(* Logix 5000 project; controller DNP3Master vendor 1 type 14 code 96 rev 19.13; software revision 19.01; part 4 of 5 *)

ADD_ON_INSTRUCTION PSDNP3EventG30V02   (* revision 1.0, vendor ProSoft Technology Inc *)
// Processes DNP3 Event and updates corresponding static DNP3 object. (Report by Exception.)
// G30V01 - Analog Input - 16bit with Status
VAR_IN_OUT
   EventBuffer : PSDNP3MasterEvent[1]; {required}
END_VAR
VAR_INPUT
   BufferSize : DINT; {required}
   CurrentBufferIndex : DINT; {required}
   Reset : BOOL; {required}
   OutstationNodeAddress : INT; {required}
   OutstationIPAddress0 : INT; {required}
   OutstationIPAddress1 : INT; {required}
   OutstationIPAddress2 : INT; {required}
   OutstationIPAddress3 : INT; {required}
END_VAR
VAR_IN_OUT
   DNP3StaticObject : PSDNP3AnalogInput16Flag[1]; {required}
END_VAR
VAR_INPUT
   MaxtElementCount : DINT; {required}
END_VAR
VAR_OUTPUT
   EventsProcessed : DINT; {access Read Only, visible}
   LastElementIndex : DINT; {access Read Only, visible}
   LastValue : DINT; {access Read Only, visible}
   LastStatus : SINT; {access Read Only, visible}
   CurrentUnloadIndex : DINT; {access Read Only, visible}
END_VAR
VAR
   UnloadIndex : DINT; {access None}
   EnableInTemp : BOOL; {access None}
   InitialScan : BOOL; {access None}
   EntryValidForProcessing : BOOL; {access None}
   ElementIndex : DINT; {access None}
   NextIndex : DINT; {access None}
   ResetPulse : BOOL; {access None}
   ResetONS : BOOL; {access None}
END_VAR

ROUTINE Logic   (* ladder *)
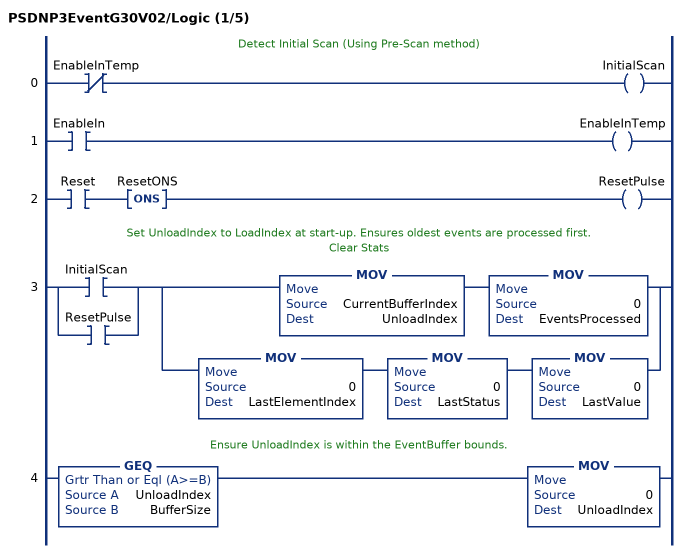
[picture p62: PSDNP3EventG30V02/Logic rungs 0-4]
   // Detect Initial Scan (Using Pre-Scan method)
   0: XIO(EnableInTemp)OTE(InitialScan);
   1: XIC(EnableIn)OTE(EnableInTemp);
   2: XIC(Reset)ONS(ResetONS)OTE(ResetPulse);
   // Set UnloadIndex to LoadIndex at start-up. Ensures oldest events are processed first.
   // Clear Stats
   3: [XIC(InitialScan) ,XIC(ResetPulse) ][MOV(CurrentBufferIndex,UnloadIndex) MOV(0,EventsProcessed) ,MOV(0,LastElementIndex) MOV(0,LastStatus) MOV(0,LastValue) ];
   // Ensure UnloadIndex is within the EventBuffer bounds.
   4: GEQ(UnloadIndex,BufferSize)MOV(0,UnloadIndex);
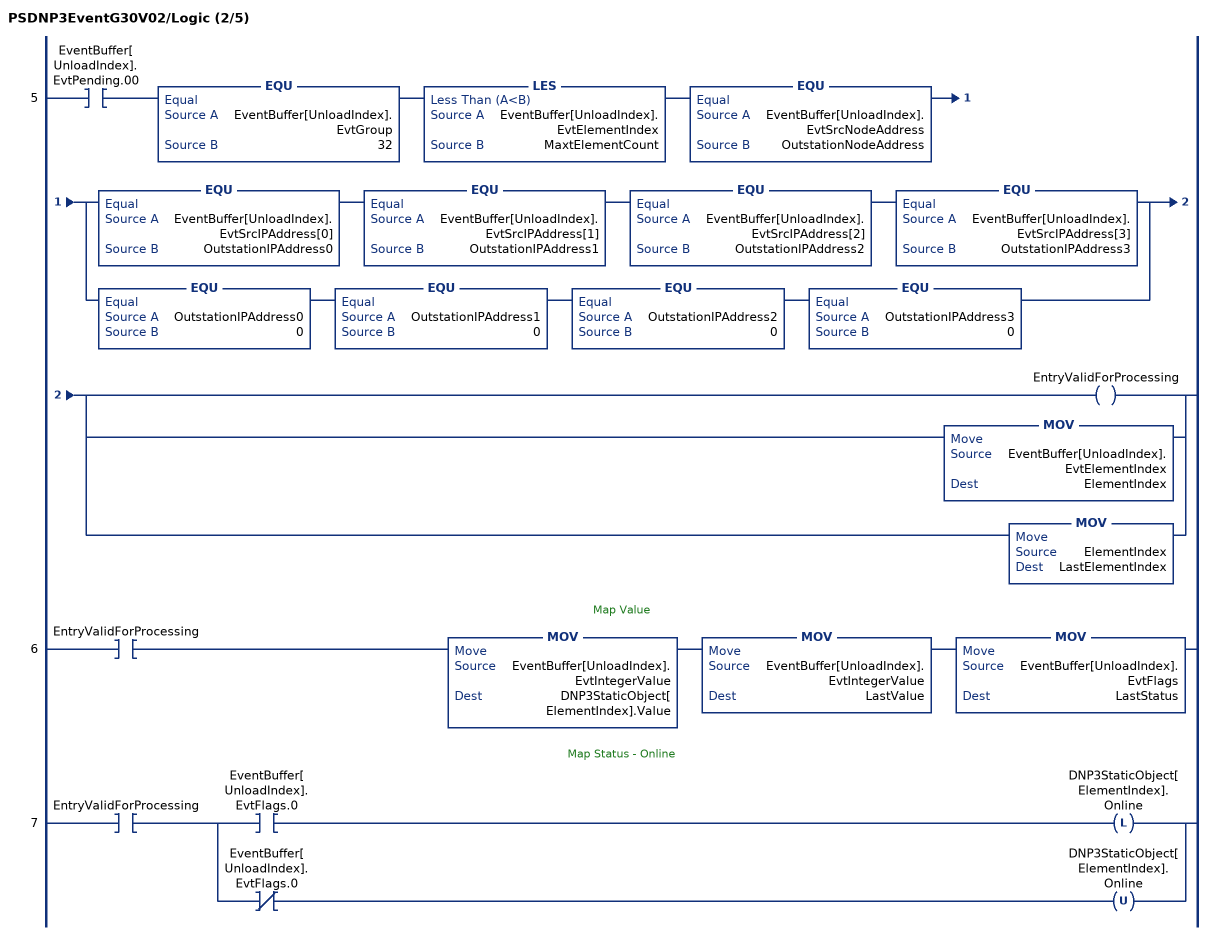
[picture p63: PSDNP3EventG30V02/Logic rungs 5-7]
   5: XIC(EventBuffer[UnloadIndex].EvtPending.00)EQU(EventBuffer[UnloadIndex].EvtGroup,32)LES(EventBuffer[UnloadIndex].EvtElementIndex,MaxtElementCount)EQU(EventBuffer[UnloadIndex].EvtSrcNodeAddress,OutstationNodeAddress)[EQU(EventBuffer[UnloadIndex].EvtSrcIPAddress[0],OutstationIPAddress0) EQU(EventBuffer[UnloadIndex].EvtSrcIPAddress[1],OutstationIPAddress1) EQU(EventBuffer[UnloadIndex].EvtSrcIPAddress[2],OutstationIPAddress2) EQU(EventBuffer[UnloadIndex].EvtSrcIPAddress[3],OutstationIPAddress3) ,EQU(OutstationIPAddress0,0) EQU(OutstationIPAddress1,0) EQU(OutstationIPAddress2,0) EQU(OutstationIPAddress3,0) ][OTE(EntryValidForProcessing) ,MOV(EventBuffer[UnloadIndex].EvtElementIndex,ElementIndex) ,MOV(ElementIndex,LastElementIndex) ];
   // Map Value
   6: XIC(EntryValidForProcessing)MOV(EventBuffer[UnloadIndex].EvtIntegerValue,DNP3StaticObject[ElementIndex].Value)MOV(EventBuffer[UnloadIndex].EvtIntegerValue,LastValue)MOV(EventBuffer[UnloadIndex].EvtFlags,LastStatus);
   // Map Status - Online
   7: XIC(EntryValidForProcessing)[XIC(EventBuffer[UnloadIndex].EvtFlags.0) OTL(DNP3StaticObject[ElementIndex].Online) ,XIO(EventBuffer[UnloadIndex].EvtFlags.0) OTU(DNP3StaticObject[ElementIndex].Online) ];
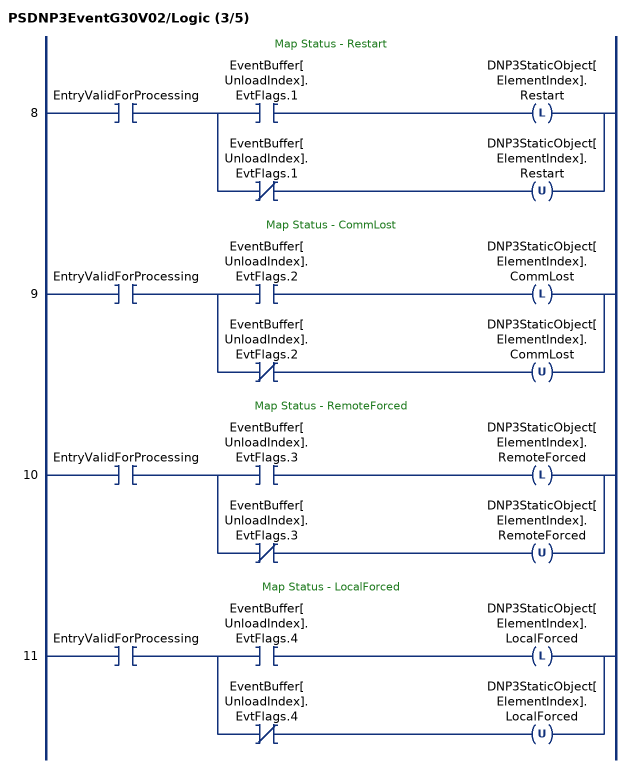
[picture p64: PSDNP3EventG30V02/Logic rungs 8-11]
   // Map Status - Restart
   8: XIC(EntryValidForProcessing)[XIC(EventBuffer[UnloadIndex].EvtFlags.1) OTL(DNP3StaticObject[ElementIndex].Restart) ,XIO(EventBuffer[UnloadIndex].EvtFlags.1) OTU(DNP3StaticObject[ElementIndex].Restart) ];
   // Map Status - CommLost
   9: XIC(EntryValidForProcessing)[XIC(EventBuffer[UnloadIndex].EvtFlags.2) OTL(DNP3StaticObject[ElementIndex].CommLost) ,XIO(EventBuffer[UnloadIndex].EvtFlags.2) OTU(DNP3StaticObject[ElementIndex].CommLost) ];
   // Map Status - RemoteForced
   10: XIC(EntryValidForProcessing)[XIC(EventBuffer[UnloadIndex].EvtFlags.3) OTL(DNP3StaticObject[ElementIndex].RemoteForced) ,XIO(EventBuffer[UnloadIndex].EvtFlags.3) OTU(DNP3StaticObject[ElementIndex].RemoteForced) ];
   // Map Status - LocalForced
   11: XIC(EntryValidForProcessing)[XIC(EventBuffer[UnloadIndex].EvtFlags.4) OTL(DNP3StaticObject[ElementIndex].LocalForced) ,XIO(EventBuffer[UnloadIndex].EvtFlags.4) OTU(DNP3StaticObject[ElementIndex].LocalForced) ];
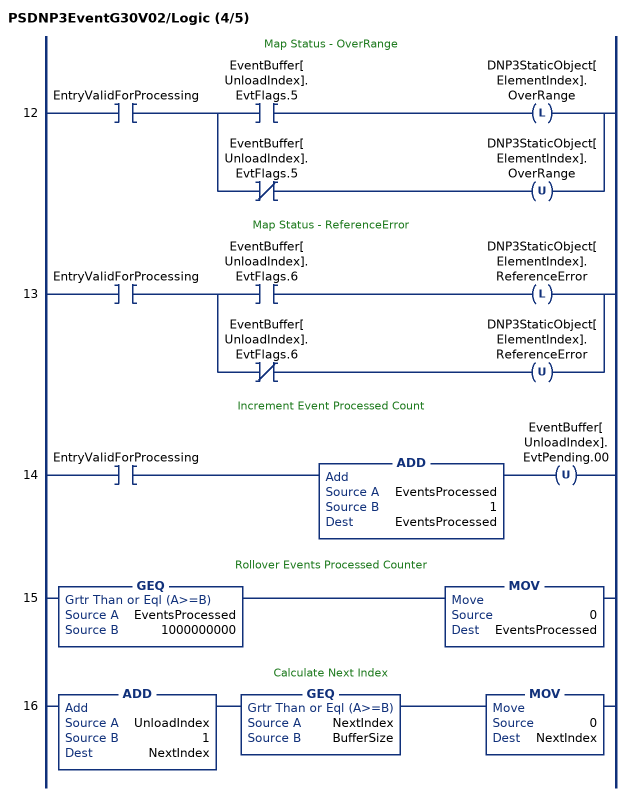
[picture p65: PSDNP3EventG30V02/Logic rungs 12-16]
   // Map Status - OverRange
   12: XIC(EntryValidForProcessing)[XIC(EventBuffer[UnloadIndex].EvtFlags.5) OTL(DNP3StaticObject[ElementIndex].OverRange) ,XIO(EventBuffer[UnloadIndex].EvtFlags.5) OTU(DNP3StaticObject[ElementIndex].OverRange) ];
   // Map Status - ReferenceError
   13: XIC(EntryValidForProcessing)[XIC(EventBuffer[UnloadIndex].EvtFlags.6) OTL(DNP3StaticObject[ElementIndex].ReferenceError) ,XIO(EventBuffer[UnloadIndex].EvtFlags.6) OTU(DNP3StaticObject[ElementIndex].ReferenceError) ];
   // Increment Event Processed Count
   14: XIC(EntryValidForProcessing)ADD(EventsProcessed,1,EventsProcessed)OTU(EventBuffer[UnloadIndex].EvtPending.00);
   // Rollover Events Processed Counter
   15: GEQ(EventsProcessed,1000000000)MOV(0,EventsProcessed);
   // Calculate Next Index
   16: ADD(UnloadIndex,1,NextIndex)GEQ(NextIndex,BufferSize)MOV(0,NextIndex);
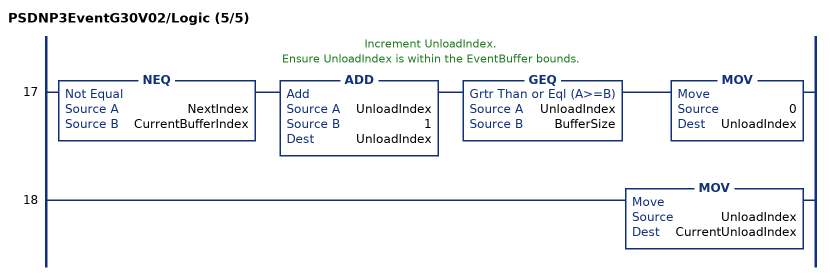
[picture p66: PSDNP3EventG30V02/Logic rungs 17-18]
   // Increment UnloadIndex.
   // Ensure UnloadIndex is within the EventBuffer bounds.
   17: NEQ(NextIndex,CurrentBufferIndex)ADD(UnloadIndex,1,UnloadIndex)GEQ(UnloadIndex,BufferSize)MOV(0,UnloadIndex);
   18: MOV(UnloadIndex,CurrentUnloadIndex);
END_ROUTINE
END_ADD_ON_INSTRUCTION

ADD_ON_INSTRUCTION PSDNP3EventG30V03   (* revision 1.0, vendor ProSoft Technology Inc *)
// Processes DNP3 Event and updates corresponding static DNP3 object. (Report by Exception.)
// G30V03 - Analog Input - 32bit no Status
VAR_IN_OUT
   EventBuffer : PSDNP3MasterEvent[1]; {required}
END_VAR
VAR_INPUT
   BufferSize : DINT; {required}
   CurrentBufferIndex : DINT; {required}
   Reset : BOOL; {required}
   OutstationNodeAddress : INT; {required}
   OutstationIPAddress0 : INT; {required}
   OutstationIPAddress1 : INT; {required}
   OutstationIPAddress2 : INT; {required}
   OutstationIPAddress3 : INT; {required}
END_VAR
VAR_IN_OUT
   DNP3StaticObject : DINT[1]; {required}
END_VAR
VAR_INPUT
   MaxtElementCount : DINT; {required}
END_VAR
VAR_OUTPUT
   EventsProcessed : DINT; {access Read Only, visible}
   LastElementIndex : DINT; {access Read Only, visible}
   LastValue : DINT; {access Read Only, visible}
   LastStatus : SINT; {access Read Only, visible}
   CurrentUnloadIndex : DINT; {access Read Only, visible}
END_VAR
VAR
   UnloadIndex : DINT; {access None}
   EnableInTemp : BOOL; {access None}
   InitialScan : BOOL; {access None}
   EntryValidForProcessing : BOOL; {access None}
   ElementIndex : DINT; {access None}
   NextIndex : DINT; {access None}
   ResetPulse : BOOL; {access None}
   ResetONS : BOOL; {access None}
END_VAR

ROUTINE Logic   (* ladder *)
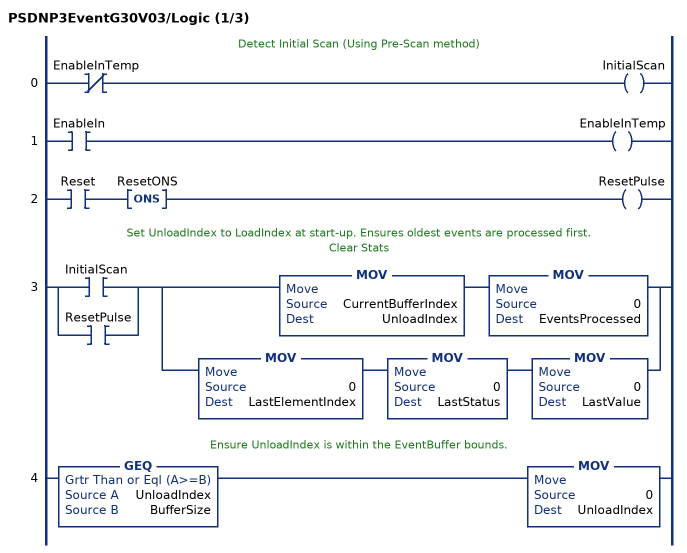
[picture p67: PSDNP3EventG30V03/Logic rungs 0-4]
   // Detect Initial Scan (Using Pre-Scan method)
   0: XIO(EnableInTemp)OTE(InitialScan);
   1: XIC(EnableIn)OTE(EnableInTemp);
   2: XIC(Reset)ONS(ResetONS)OTE(ResetPulse);
   // Set UnloadIndex to LoadIndex at start-up. Ensures oldest events are processed first.
   // Clear Stats
   3: [XIC(InitialScan) ,XIC(ResetPulse) ][MOV(CurrentBufferIndex,UnloadIndex) MOV(0,EventsProcessed) ,MOV(0,LastElementIndex) MOV(0,LastStatus) MOV(0,LastValue) ];
   // Ensure UnloadIndex is within the EventBuffer bounds.
   4: GEQ(UnloadIndex,BufferSize)MOV(0,UnloadIndex);
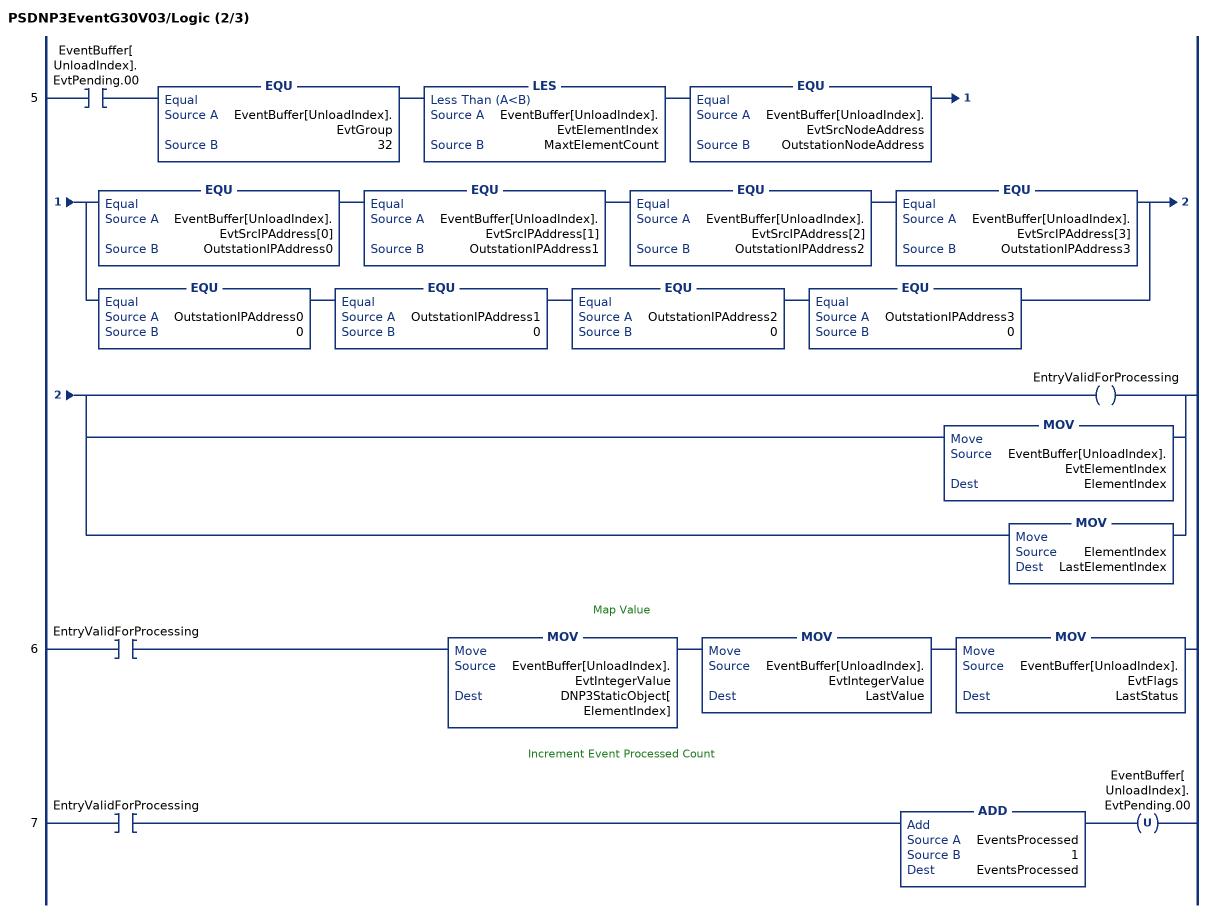
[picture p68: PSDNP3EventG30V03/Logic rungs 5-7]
   5: XIC(EventBuffer[UnloadIndex].EvtPending.00)EQU(EventBuffer[UnloadIndex].EvtGroup,32)LES(EventBuffer[UnloadIndex].EvtElementIndex,MaxtElementCount)EQU(EventBuffer[UnloadIndex].EvtSrcNodeAddress,OutstationNodeAddress)[EQU(EventBuffer[UnloadIndex].EvtSrcIPAddress[0],OutstationIPAddress0) EQU(EventBuffer[UnloadIndex].EvtSrcIPAddress[1],OutstationIPAddress1) EQU(EventBuffer[UnloadIndex].EvtSrcIPAddress[2],OutstationIPAddress2) EQU(EventBuffer[UnloadIndex].EvtSrcIPAddress[3],OutstationIPAddress3) ,EQU(OutstationIPAddress0,0) EQU(OutstationIPAddress1,0) EQU(OutstationIPAddress2,0) EQU(OutstationIPAddress3,0) ][OTE(EntryValidForProcessing) ,MOV(EventBuffer[UnloadIndex].EvtElementIndex,ElementIndex) ,MOV(ElementIndex,LastElementIndex) ];
   // Map Value
   6: XIC(EntryValidForProcessing)MOV(EventBuffer[UnloadIndex].EvtIntegerValue,DNP3StaticObject[ElementIndex])MOV(EventBuffer[UnloadIndex].EvtIntegerValue,LastValue)MOV(EventBuffer[UnloadIndex].EvtFlags,LastStatus);
   // Increment Event Processed Count
   7: XIC(EntryValidForProcessing)ADD(EventsProcessed,1,EventsProcessed)OTU(EventBuffer[UnloadIndex].EvtPending.00);
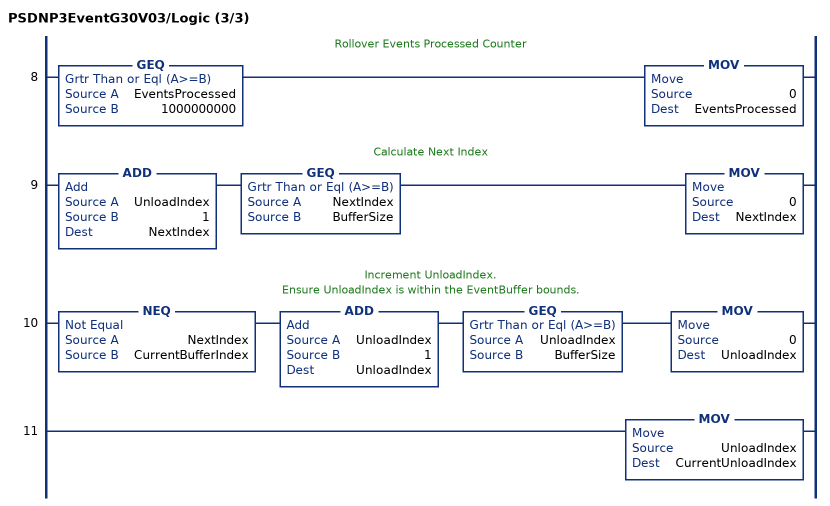
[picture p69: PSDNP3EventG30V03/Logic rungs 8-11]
   // Rollover Events Processed Counter
   8: GEQ(EventsProcessed,1000000000)MOV(0,EventsProcessed);
   // Calculate Next Index
   9: ADD(UnloadIndex,1,NextIndex)GEQ(NextIndex,BufferSize)MOV(0,NextIndex);
   // Increment UnloadIndex.
   // Ensure UnloadIndex is within the EventBuffer bounds.
   10: NEQ(NextIndex,CurrentBufferIndex)ADD(UnloadIndex,1,UnloadIndex)GEQ(UnloadIndex,BufferSize)MOV(0,UnloadIndex);
   11: MOV(UnloadIndex,CurrentUnloadIndex);
END_ROUTINE
END_ADD_ON_INSTRUCTION

ADD_ON_INSTRUCTION PSDNP3EventG30V04   (* revision 1.0, vendor ProSoft Technology Inc *)
// Processes DNP3 Event and updates corresponding static DNP3 object. (Report by Exception.)
// G30V04 - Analog Input - 16bit no Status
VAR_IN_OUT
   EventBuffer : PSDNP3MasterEvent[1]; {required}
END_VAR
VAR_INPUT
   BufferSize : DINT; {required}
   CurrentBufferIndex : DINT; {required}
   Reset : BOOL; {required}
   OutstationNodeAddress : INT; {required}
   OutstationIPAddress0 : INT; {required}
   OutstationIPAddress1 : INT; {required}
   OutstationIPAddress2 : INT; {required}
   OutstationIPAddress3 : INT; {required}
END_VAR
VAR_IN_OUT
   DNP3StaticObject : INT[1]; {required}
END_VAR
VAR_INPUT
   MaxtElementCount : DINT; {required}
END_VAR
VAR_OUTPUT
   EventsProcessed : DINT; {access Read Only, visible}
   LastElementIndex : DINT; {access Read Only, visible}
   LastValue : DINT; {access Read Only, visible}
   LastStatus : SINT; {access Read Only, visible}
   CurrentUnloadIndex : DINT; {access Read Only, visible}
END_VAR
VAR
   UnloadIndex : DINT; {access None}
   EnableInTemp : BOOL; {access None}
   InitialScan : BOOL; {access None}
   EntryValidForProcessing : BOOL; {access None}
   ElementIndex : DINT; {access None}
   NextIndex : DINT; {access None}
   ResetPulse : BOOL; {access None}
   ResetONS : BOOL; {access None}
END_VAR

ROUTINE Logic   (* ladder *)
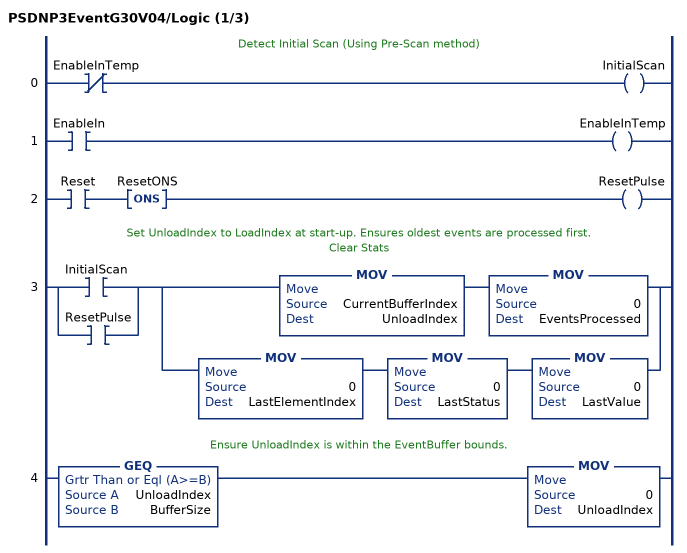
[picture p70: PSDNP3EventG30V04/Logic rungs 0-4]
   // Detect Initial Scan (Using Pre-Scan method)
   0: XIO(EnableInTemp)OTE(InitialScan);
   1: XIC(EnableIn)OTE(EnableInTemp);
   2: XIC(Reset)ONS(ResetONS)OTE(ResetPulse);
   // Set UnloadIndex to LoadIndex at start-up. Ensures oldest events are processed first.
   // Clear Stats
   3: [XIC(InitialScan) ,XIC(ResetPulse) ][MOV(CurrentBufferIndex,UnloadIndex) MOV(0,EventsProcessed) ,MOV(0,LastElementIndex) MOV(0,LastStatus) MOV(0,LastValue) ];
   // Ensure UnloadIndex is within the EventBuffer bounds.
   4: GEQ(UnloadIndex,BufferSize)MOV(0,UnloadIndex);
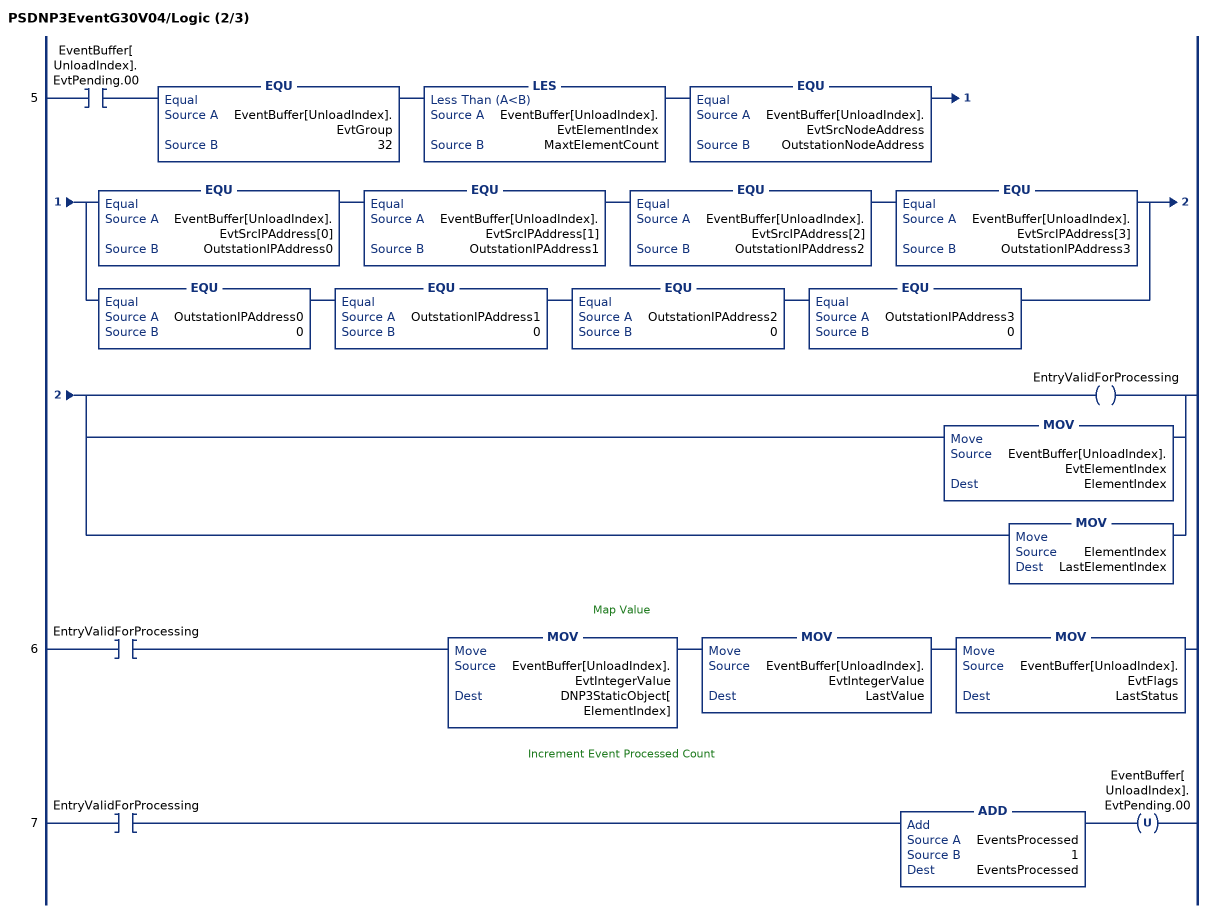
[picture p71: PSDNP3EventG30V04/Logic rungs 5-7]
   5: XIC(EventBuffer[UnloadIndex].EvtPending.00)EQU(EventBuffer[UnloadIndex].EvtGroup,32)LES(EventBuffer[UnloadIndex].EvtElementIndex,MaxtElementCount)EQU(EventBuffer[UnloadIndex].EvtSrcNodeAddress,OutstationNodeAddress)[EQU(EventBuffer[UnloadIndex].EvtSrcIPAddress[0],OutstationIPAddress0) EQU(EventBuffer[UnloadIndex].EvtSrcIPAddress[1],OutstationIPAddress1) EQU(EventBuffer[UnloadIndex].EvtSrcIPAddress[2],OutstationIPAddress2) EQU(EventBuffer[UnloadIndex].EvtSrcIPAddress[3],OutstationIPAddress3) ,EQU(OutstationIPAddress0,0) EQU(OutstationIPAddress1,0) EQU(OutstationIPAddress2,0) EQU(OutstationIPAddress3,0) ][OTE(EntryValidForProcessing) ,MOV(EventBuffer[UnloadIndex].EvtElementIndex,ElementIndex) ,MOV(ElementIndex,LastElementIndex) ];
   // Map Value
   6: XIC(EntryValidForProcessing)MOV(EventBuffer[UnloadIndex].EvtIntegerValue,DNP3StaticObject[ElementIndex])MOV(EventBuffer[UnloadIndex].EvtIntegerValue,LastValue)MOV(EventBuffer[UnloadIndex].EvtFlags,LastStatus);
   // Increment Event Processed Count
   7: XIC(EntryValidForProcessing)ADD(EventsProcessed,1,EventsProcessed)OTU(EventBuffer[UnloadIndex].EvtPending.00);
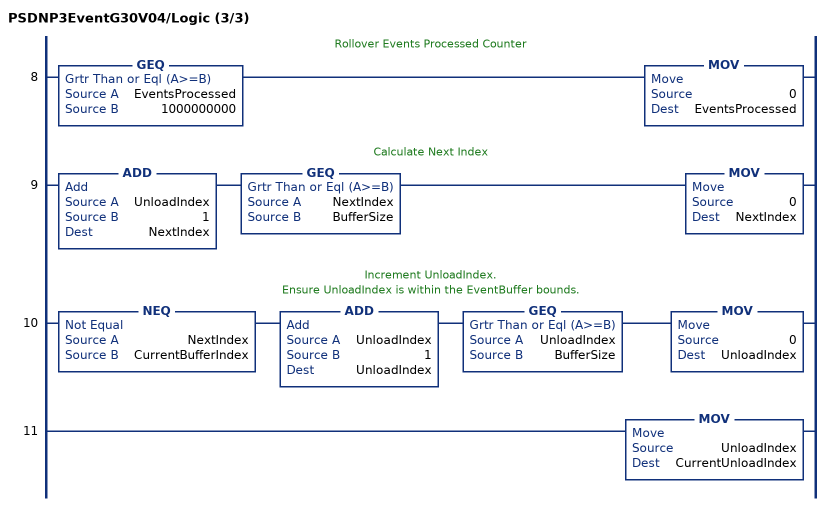
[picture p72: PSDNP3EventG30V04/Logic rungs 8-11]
   // Rollover Events Processed Counter
   8: GEQ(EventsProcessed,1000000000)MOV(0,EventsProcessed);
   // Calculate Next Index
   9: ADD(UnloadIndex,1,NextIndex)GEQ(NextIndex,BufferSize)MOV(0,NextIndex);
   // Increment UnloadIndex.
   // Ensure UnloadIndex is within the EventBuffer bounds.
   10: NEQ(NextIndex,CurrentBufferIndex)ADD(UnloadIndex,1,UnloadIndex)GEQ(UnloadIndex,BufferSize)MOV(0,UnloadIndex);
   11: MOV(UnloadIndex,CurrentUnloadIndex);
END_ROUTINE
END_ADD_ON_INSTRUCTION

ADD_ON_INSTRUCTION PSDNP3EventG30V05   (* revision 1.0, vendor ProSoft Technology Inc *)
// Processes DNP3 Event and updates corresponding static DNP3 object. (Report by Exception.)
// G30V05 - Analog Input - Real with Status
VAR_IN_OUT
   EventBuffer : PSDNP3MasterEvent[1]; {required}
END_VAR
VAR_INPUT
   BufferSize : DINT; {required}
   CurrentBufferIndex : DINT; {required}
   Reset : BOOL; {required}
   OutstationNodeAddress : INT; {required}
   OutstationIPAddress0 : INT; {required}
   OutstationIPAddress1 : INT; {required}
   OutstationIPAddress2 : INT; {required}
   OutstationIPAddress3 : INT; {required}
END_VAR
VAR_IN_OUT
   DNP3StaticObject : PSDNP3AnalogInputRealFlag[1]; {required}
END_VAR
VAR_INPUT
   MaxtElementCount : DINT; {required}
END_VAR
VAR_OUTPUT
   EventsProcessed : DINT; {access Read Only, visible}
   LastElementIndex : DINT; {access Read Only, visible}
   LastValue : REAL; {access Read Only, visible}
   LastStatus : SINT; {access Read Only, visible}
   CurrentUnloadIndex : DINT; {access Read Only, visible}
END_VAR
VAR
   UnloadIndex : DINT; {access None}
   EnableInTemp : BOOL; {access None}
   InitialScan : BOOL; {access None}
   EntryValidForProcessing : BOOL; {access None}
   ElementIndex : DINT; {access None}
   NextIndex : DINT; {access None}
   ResetPulse : BOOL; {access None}
   ResetONS : BOOL; {access None}
END_VAR

ROUTINE Logic   (* ladder *)
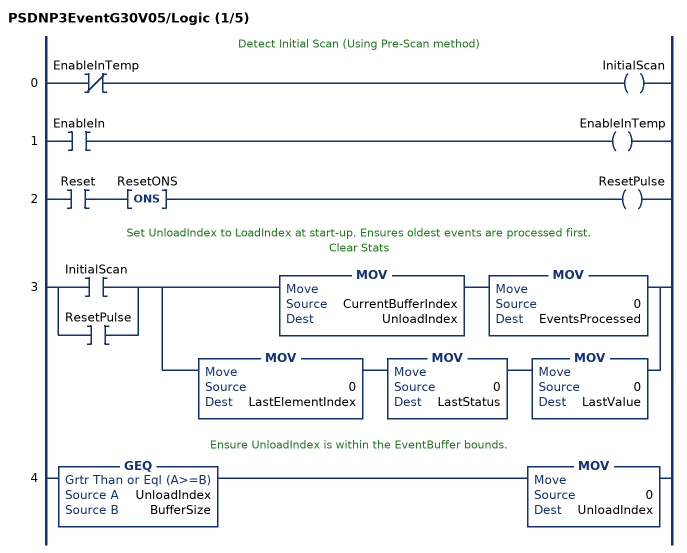
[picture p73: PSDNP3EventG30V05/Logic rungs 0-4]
   // Detect Initial Scan (Using Pre-Scan method)
   0: XIO(EnableInTemp)OTE(InitialScan);
   1: XIC(EnableIn)OTE(EnableInTemp);
   2: XIC(Reset)ONS(ResetONS)OTE(ResetPulse);
   // Set UnloadIndex to LoadIndex at start-up. Ensures oldest events are processed first.
   // Clear Stats
   3: [XIC(InitialScan) ,XIC(ResetPulse) ][MOV(CurrentBufferIndex,UnloadIndex) MOV(0,EventsProcessed) ,MOV(0,LastElementIndex) MOV(0,LastStatus) MOV(0,LastValue) ];
   // Ensure UnloadIndex is within the EventBuffer bounds.
   4: GEQ(UnloadIndex,BufferSize)MOV(0,UnloadIndex);
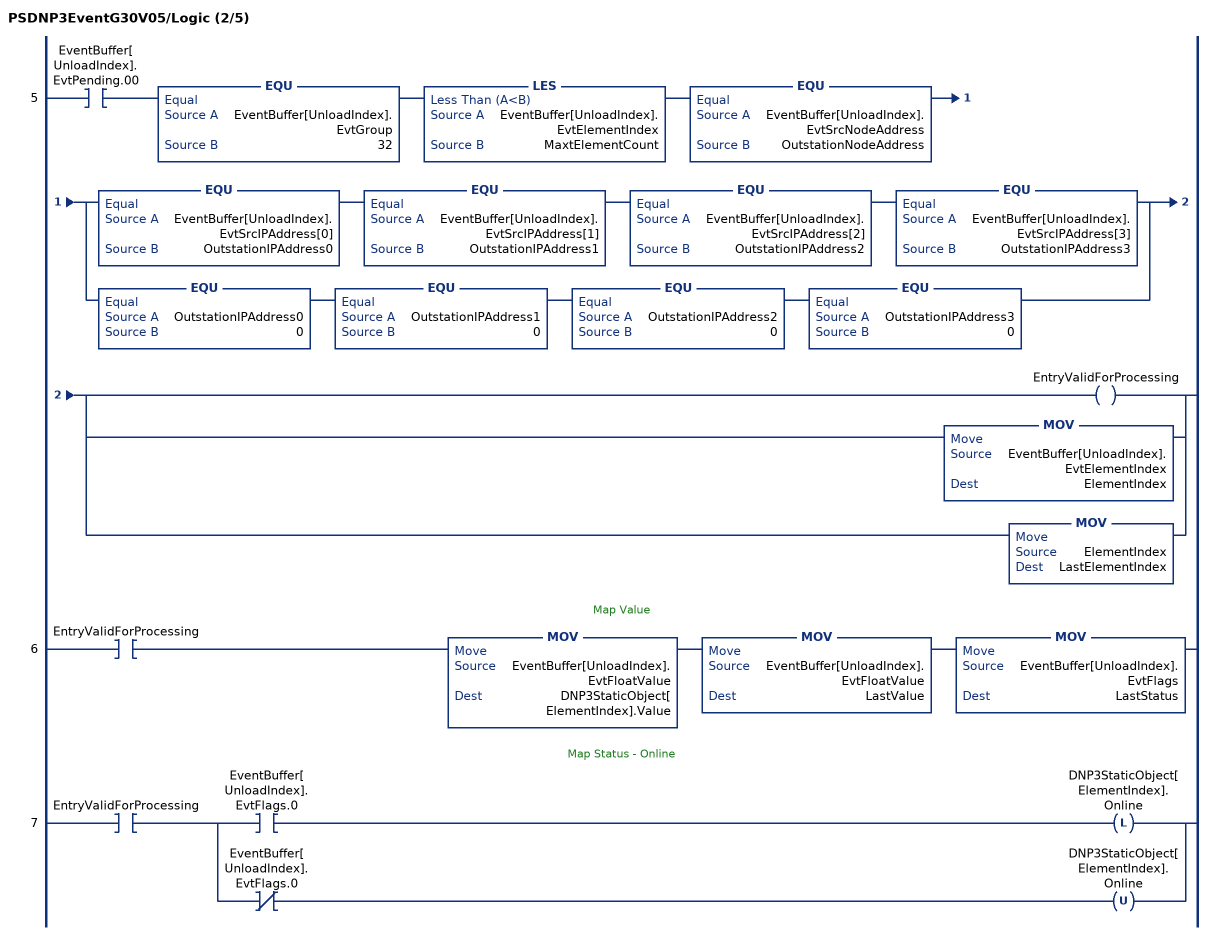
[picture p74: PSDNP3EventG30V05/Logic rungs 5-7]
   5: XIC(EventBuffer[UnloadIndex].EvtPending.00)EQU(EventBuffer[UnloadIndex].EvtGroup,32)LES(EventBuffer[UnloadIndex].EvtElementIndex,MaxtElementCount)EQU(EventBuffer[UnloadIndex].EvtSrcNodeAddress,OutstationNodeAddress)[EQU(EventBuffer[UnloadIndex].EvtSrcIPAddress[0],OutstationIPAddress0) EQU(EventBuffer[UnloadIndex].EvtSrcIPAddress[1],OutstationIPAddress1) EQU(EventBuffer[UnloadIndex].EvtSrcIPAddress[2],OutstationIPAddress2) EQU(EventBuffer[UnloadIndex].EvtSrcIPAddress[3],OutstationIPAddress3) ,EQU(OutstationIPAddress0,0) EQU(OutstationIPAddress1,0) EQU(OutstationIPAddress2,0) EQU(OutstationIPAddress3,0) ][OTE(EntryValidForProcessing) ,MOV(EventBuffer[UnloadIndex].EvtElementIndex,ElementIndex) ,MOV(ElementIndex,LastElementIndex) ];
   // Map Value
   6: XIC(EntryValidForProcessing)MOV(EventBuffer[UnloadIndex].EvtFloatValue,DNP3StaticObject[ElementIndex].Value)MOV(EventBuffer[UnloadIndex].EvtFloatValue,LastValue)MOV(EventBuffer[UnloadIndex].EvtFlags,LastStatus);
   // Map Status - Online
   7: XIC(EntryValidForProcessing)[XIC(EventBuffer[UnloadIndex].EvtFlags.0) OTL(DNP3StaticObject[ElementIndex].Online) ,XIO(EventBuffer[UnloadIndex].EvtFlags.0) OTU(DNP3StaticObject[ElementIndex].Online) ];
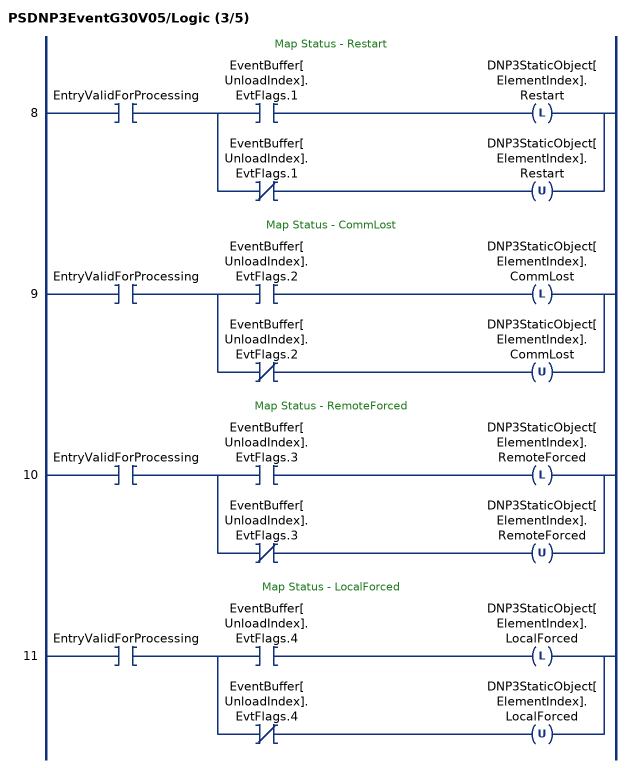
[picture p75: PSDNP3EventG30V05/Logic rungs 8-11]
   // Map Status - Restart
   8: XIC(EntryValidForProcessing)[XIC(EventBuffer[UnloadIndex].EvtFlags.1) OTL(DNP3StaticObject[ElementIndex].Restart) ,XIO(EventBuffer[UnloadIndex].EvtFlags.1) OTU(DNP3StaticObject[ElementIndex].Restart) ];
   // Map Status - CommLost
   9: XIC(EntryValidForProcessing)[XIC(EventBuffer[UnloadIndex].EvtFlags.2) OTL(DNP3StaticObject[ElementIndex].CommLost) ,XIO(EventBuffer[UnloadIndex].EvtFlags.2) OTU(DNP3StaticObject[ElementIndex].CommLost) ];
   // Map Status - RemoteForced
   10: XIC(EntryValidForProcessing)[XIC(EventBuffer[UnloadIndex].EvtFlags.3) OTL(DNP3StaticObject[ElementIndex].RemoteForced) ,XIO(EventBuffer[UnloadIndex].EvtFlags.3) OTU(DNP3StaticObject[ElementIndex].RemoteForced) ];
   // Map Status - LocalForced
   11: XIC(EntryValidForProcessing)[XIC(EventBuffer[UnloadIndex].EvtFlags.4) OTL(DNP3StaticObject[ElementIndex].LocalForced) ,XIO(EventBuffer[UnloadIndex].EvtFlags.4) OTU(DNP3StaticObject[ElementIndex].LocalForced) ];
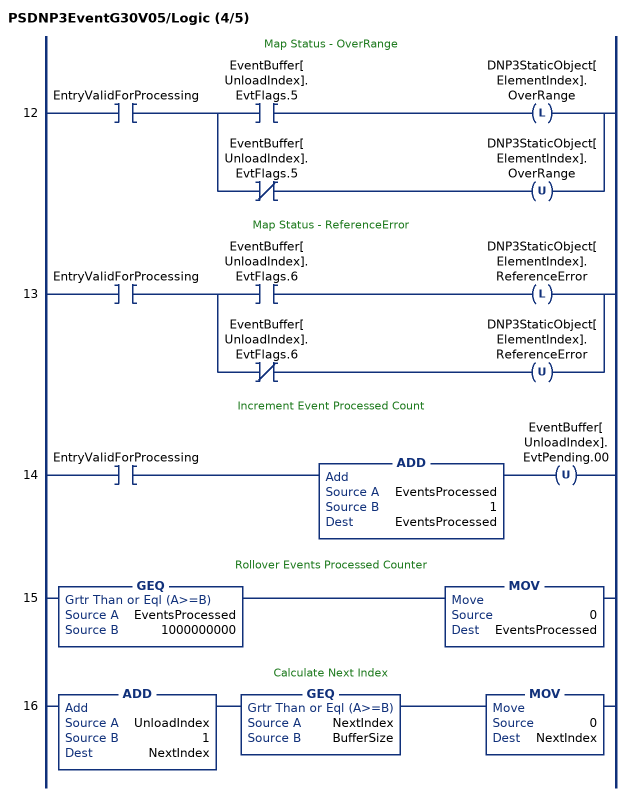
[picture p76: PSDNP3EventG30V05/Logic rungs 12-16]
   // Map Status - OverRange
   12: XIC(EntryValidForProcessing)[XIC(EventBuffer[UnloadIndex].EvtFlags.5) OTL(DNP3StaticObject[ElementIndex].OverRange) ,XIO(EventBuffer[UnloadIndex].EvtFlags.5) OTU(DNP3StaticObject[ElementIndex].OverRange) ];
   // Map Status - ReferenceError
   13: XIC(EntryValidForProcessing)[XIC(EventBuffer[UnloadIndex].EvtFlags.6) OTL(DNP3StaticObject[ElementIndex].ReferenceError) ,XIO(EventBuffer[UnloadIndex].EvtFlags.6) OTU(DNP3StaticObject[ElementIndex].ReferenceError) ];
   // Increment Event Processed Count
   14: XIC(EntryValidForProcessing)ADD(EventsProcessed,1,EventsProcessed)OTU(EventBuffer[UnloadIndex].EvtPending.00);
   // Rollover Events Processed Counter
   15: GEQ(EventsProcessed,1000000000)MOV(0,EventsProcessed);
   // Calculate Next Index
   16: ADD(UnloadIndex,1,NextIndex)GEQ(NextIndex,BufferSize)MOV(0,NextIndex);
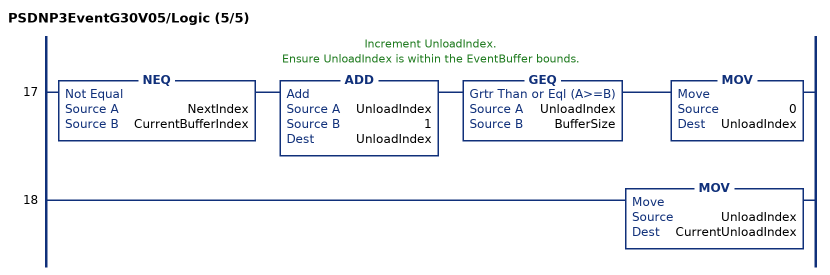
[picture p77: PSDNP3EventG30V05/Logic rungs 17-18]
   // Increment UnloadIndex.
   // Ensure UnloadIndex is within the EventBuffer bounds.
   17: NEQ(NextIndex,CurrentBufferIndex)ADD(UnloadIndex,1,UnloadIndex)GEQ(UnloadIndex,BufferSize)MOV(0,UnloadIndex);
   18: MOV(UnloadIndex,CurrentUnloadIndex);
END_ROUTINE
END_ADD_ON_INSTRUCTION

ADD_ON_INSTRUCTION PSDNP3EventG40V01   (* revision 1.0, vendor ProSoft Technology Inc *)
// Processes DNP3 Event and updates corresponding static DNP3 object. (Report by Exception.)
// G40V01 - Analog Output Status - 32bit with Status
VAR_IN_OUT
   EventBuffer : PSDNP3MasterEvent[1]; {required}
END_VAR
VAR_INPUT
   BufferSize : DINT; {required}
   CurrentBufferIndex : DINT; {required}
   Reset : BOOL; {required}
   OutstationNodeAddress : INT; {required}
   OutstationIPAddress0 : INT; {required}
   OutstationIPAddress1 : INT; {required}
   OutstationIPAddress2 : INT; {required}
   OutstationIPAddress3 : INT; {required}
END_VAR
VAR_IN_OUT
   DNP3StaticObject : PSDNP3AnalogOutputStatus32Flag[1]; {required}
END_VAR
VAR_INPUT
   MaxtElementCount : DINT; {required}
END_VAR
VAR_OUTPUT
   EventsProcessed : DINT; {access Read Only, visible}
   LastElementIndex : DINT; {access Read Only, visible}
   LastValue : DINT; {access Read Only, visible}
   LastStatus : SINT; {access Read Only, visible}
   CurrentUnloadIndex : DINT; {access Read Only, visible}
END_VAR
VAR
   UnloadIndex : DINT; {access None}
   EnableInTemp : BOOL; {access None}
   InitialScan : BOOL; {access None}
   EntryValidForProcessing : BOOL; {access None}
   ElementIndex : DINT; {access None}
   NextIndex : DINT; {access None}
   ResetPulse : BOOL; {access None}
   ResetONS : BOOL; {access None}
END_VAR

ROUTINE Logic   (* ladder *)
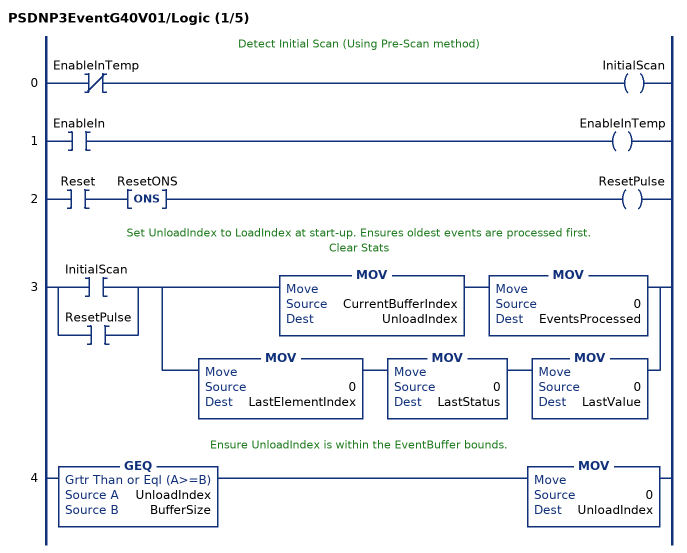
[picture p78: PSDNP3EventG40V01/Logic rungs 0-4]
   // Detect Initial Scan (Using Pre-Scan method)
   0: XIO(EnableInTemp)OTE(InitialScan);
   1: XIC(EnableIn)OTE(EnableInTemp);
   2: XIC(Reset)ONS(ResetONS)OTE(ResetPulse);
   // Set UnloadIndex to LoadIndex at start-up. Ensures oldest events are processed first.
   // Clear Stats
   3: [XIC(InitialScan) ,XIC(ResetPulse) ][MOV(CurrentBufferIndex,UnloadIndex) MOV(0,EventsProcessed) ,MOV(0,LastElementIndex) MOV(0,LastStatus) MOV(0,LastValue) ];
   // Ensure UnloadIndex is within the EventBuffer bounds.
   4: GEQ(UnloadIndex,BufferSize)MOV(0,UnloadIndex);
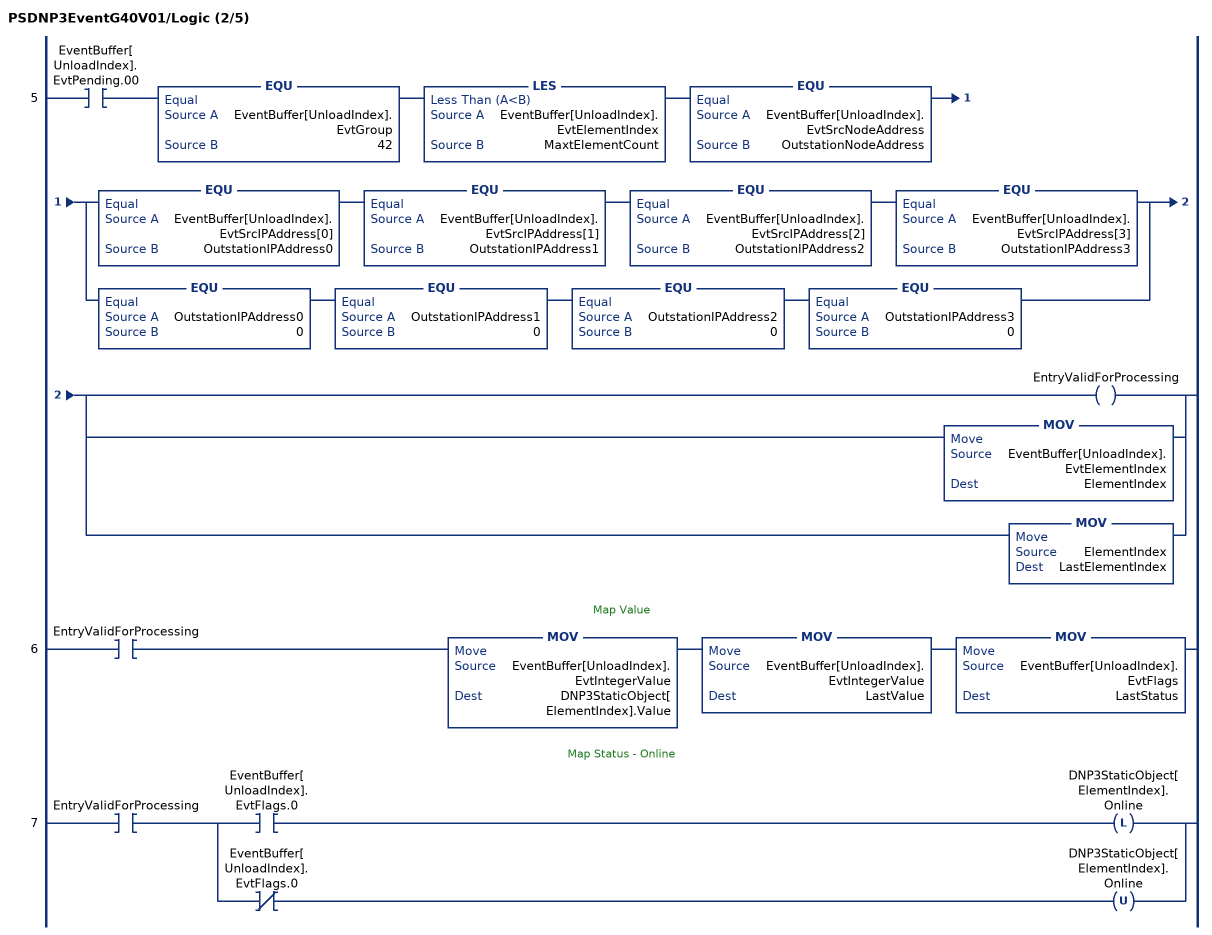
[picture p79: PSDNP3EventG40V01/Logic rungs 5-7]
   5: XIC(EventBuffer[UnloadIndex].EvtPending.00)EQU(EventBuffer[UnloadIndex].EvtGroup,42)LES(EventBuffer[UnloadIndex].EvtElementIndex,MaxtElementCount)EQU(EventBuffer[UnloadIndex].EvtSrcNodeAddress,OutstationNodeAddress)[EQU(EventBuffer[UnloadIndex].EvtSrcIPAddress[0],OutstationIPAddress0) EQU(EventBuffer[UnloadIndex].EvtSrcIPAddress[1],OutstationIPAddress1) EQU(EventBuffer[UnloadIndex].EvtSrcIPAddress[2],OutstationIPAddress2) EQU(EventBuffer[UnloadIndex].EvtSrcIPAddress[3],OutstationIPAddress3) ,EQU(OutstationIPAddress0,0) EQU(OutstationIPAddress1,0) EQU(OutstationIPAddress2,0) EQU(OutstationIPAddress3,0) ][OTE(EntryValidForProcessing) ,MOV(EventBuffer[UnloadIndex].EvtElementIndex,ElementIndex) ,MOV(ElementIndex,LastElementIndex) ];
   // Map Value
   6: XIC(EntryValidForProcessing)MOV(EventBuffer[UnloadIndex].EvtIntegerValue,DNP3StaticObject[ElementIndex].Value)MOV(EventBuffer[UnloadIndex].EvtIntegerValue,LastValue)MOV(EventBuffer[UnloadIndex].EvtFlags,LastStatus);
   // Map Status - Online
   7: XIC(EntryValidForProcessing)[XIC(EventBuffer[UnloadIndex].EvtFlags.0) OTL(DNP3StaticObject[ElementIndex].Online) ,XIO(EventBuffer[UnloadIndex].EvtFlags.0) OTU(DNP3StaticObject[ElementIndex].Online) ];
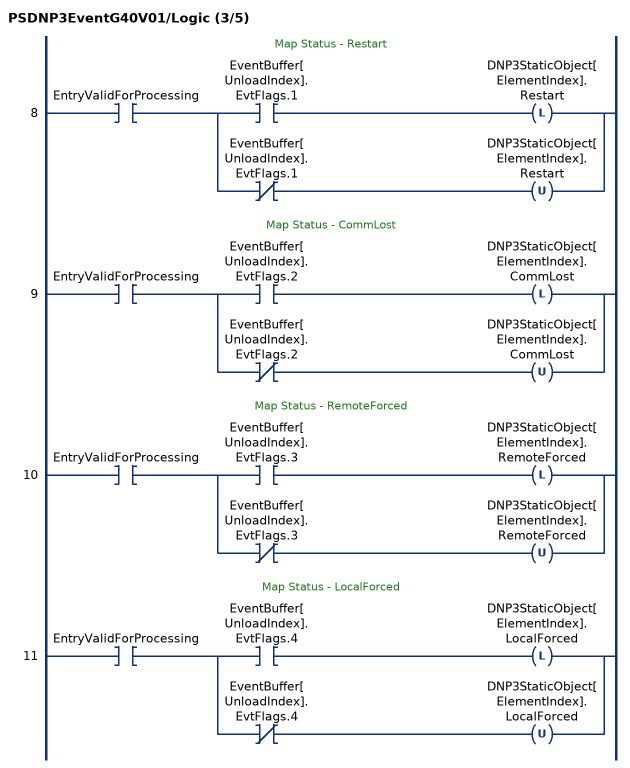
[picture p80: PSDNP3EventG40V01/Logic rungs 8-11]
   // Map Status - Restart
   8: XIC(EntryValidForProcessing)[XIC(EventBuffer[UnloadIndex].EvtFlags.1) OTL(DNP3StaticObject[ElementIndex].Restart) ,XIO(EventBuffer[UnloadIndex].EvtFlags.1) OTU(DNP3StaticObject[ElementIndex].Restart) ];
   // Map Status - CommLost
   9: XIC(EntryValidForProcessing)[XIC(EventBuffer[UnloadIndex].EvtFlags.2) OTL(DNP3StaticObject[ElementIndex].CommLost) ,XIO(EventBuffer[UnloadIndex].EvtFlags.2) OTU(DNP3StaticObject[ElementIndex].CommLost) ];
   // Map Status - RemoteForced
   10: XIC(EntryValidForProcessing)[XIC(EventBuffer[UnloadIndex].EvtFlags.3) OTL(DNP3StaticObject[ElementIndex].RemoteForced) ,XIO(EventBuffer[UnloadIndex].EvtFlags.3) OTU(DNP3StaticObject[ElementIndex].RemoteForced) ];
   // Map Status - LocalForced
   11: XIC(EntryValidForProcessing)[XIC(EventBuffer[UnloadIndex].EvtFlags.4) OTL(DNP3StaticObject[ElementIndex].LocalForced) ,XIO(EventBuffer[UnloadIndex].EvtFlags.4) OTU(DNP3StaticObject[ElementIndex].LocalForced) ];
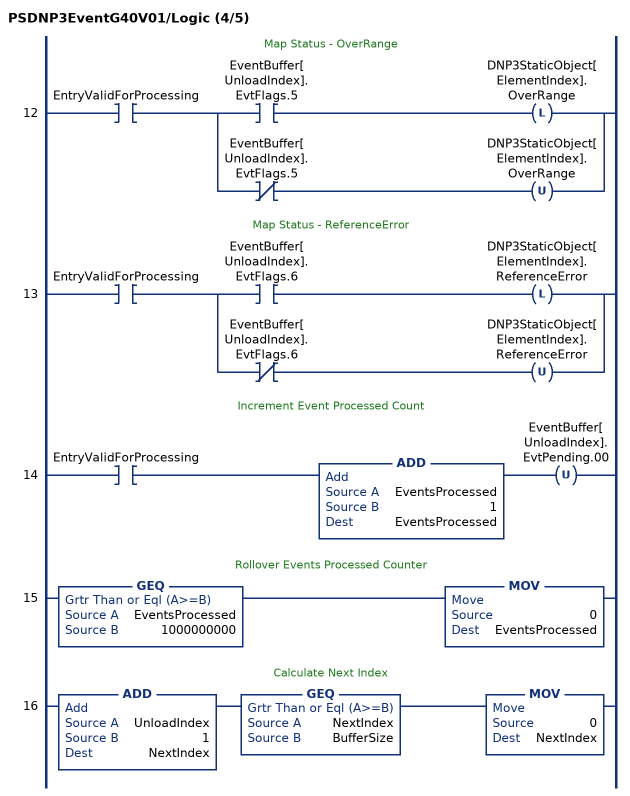
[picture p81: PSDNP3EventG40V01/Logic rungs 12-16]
   // Map Status - OverRange
   12: XIC(EntryValidForProcessing)[XIC(EventBuffer[UnloadIndex].EvtFlags.5) OTL(DNP3StaticObject[ElementIndex].OverRange) ,XIO(EventBuffer[UnloadIndex].EvtFlags.5) OTU(DNP3StaticObject[ElementIndex].OverRange) ];
   // Map Status - ReferenceError
   13: XIC(EntryValidForProcessing)[XIC(EventBuffer[UnloadIndex].EvtFlags.6) OTL(DNP3StaticObject[ElementIndex].ReferenceError) ,XIO(EventBuffer[UnloadIndex].EvtFlags.6) OTU(DNP3StaticObject[ElementIndex].ReferenceError) ];
   // Increment Event Processed Count
   14: XIC(EntryValidForProcessing)ADD(EventsProcessed,1,EventsProcessed)OTU(EventBuffer[UnloadIndex].EvtPending.00);
   // Rollover Events Processed Counter
   15: GEQ(EventsProcessed,1000000000)MOV(0,EventsProcessed);
   // Calculate Next Index
   16: ADD(UnloadIndex,1,NextIndex)GEQ(NextIndex,BufferSize)MOV(0,NextIndex);
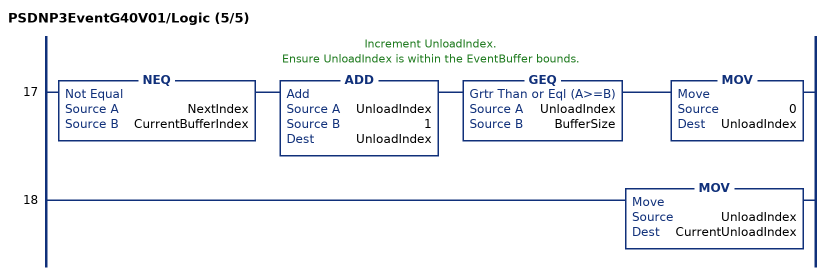
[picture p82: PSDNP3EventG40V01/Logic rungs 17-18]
   // Increment UnloadIndex.
   // Ensure UnloadIndex is within the EventBuffer bounds.
   17: NEQ(NextIndex,CurrentBufferIndex)ADD(UnloadIndex,1,UnloadIndex)GEQ(UnloadIndex,BufferSize)MOV(0,UnloadIndex);
   18: MOV(UnloadIndex,CurrentUnloadIndex);
END_ROUTINE
END_ADD_ON_INSTRUCTION
